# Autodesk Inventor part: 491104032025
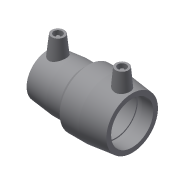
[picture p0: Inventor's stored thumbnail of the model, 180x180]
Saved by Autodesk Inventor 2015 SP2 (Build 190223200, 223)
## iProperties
Created: 2017-06
Part Number: 491104032025
Material: Generic
Description: PLASSON REDUCING COUPLER 32-25
Document SubType Name: Modeling
Designer: KIM
Mass: 54.8237 g
Surface Area: 155.252 cm^2
Volume: 54.8237 cm^3
Density: 1 g/cm^3
Appearance: Default
Author: KIM
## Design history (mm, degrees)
derived "491104.ipt"
feature "Solid1::491104.ipt"
tag "TaggingFeature1"
body "Solid1"
other parameters: "d0" = 81, "d2" = 36, "d3" = 35, "d4" = 21, "d5" = 32.4, "d7" = 25, "d8" = 168 deg, "d10" = 14, "d11" = 4.66667, "d13" = 81, "d14" = 17.6296, "d15" = 35, "d18" = 25, "d19" = 1.75, "d20" = 168 deg, "d22" = 108.92847, "d25" = 135 deg, "d29" = 39, "d30" = 15, "d31" = 28.35, "d34" = 6 deg, "d35" = 15, "d38" = 25.25, "d39" = 5 deg, "d41" = 4, "d42" = 14, "d43" = 0, "d45" = 4, "d46" = 14, "d47" = 0, "d48" = 36, "d49" = 32, "d50" = 45, "d52" = 22.5, "d53" = 16, "d54" = 5.33333, "d55" = 168 deg, "d56" = 24, "d58" = 40.5, "d59" = 1.75, "d60" = 135 deg, "d61" = 43, "d62" = 15, "d64" = 4, "d66" = 5 deg, "d67" = 14, "d68" = 0, "d69" = 28.35, "d70" = 36, "d71" = 45, "d73" = 42.3, "d76" = 1.75, "d77" = 168 deg, "d78" = 32, "d79" = 1.75, "d81" = 22.5, "d82" = 33.84, "d83" = 120 deg, "d88" = 15, "d89" = 25.4, "d90" = 5 deg, "d92" = 4, "d93" = 14, "d94" = 0, "d95" = 3, "d96" = 0, "d97" = 3, "d98" = 0, "d99" = 10.15, "d100" = 2.5375, "d101" = 32.8248, "d102" = 20 deg, "d103" = 11.6, "d104" = 2.9, "d105" = 41.031, "d106" = 3.60705, "d107" = 3, "d108" = 0, "d109" = 3, "d110" = 0, "d_1" = 25, "L_" = 81, "L_2" = 35, "D_1" = 36, "A_1" = 39, "d_2" = 12, "d_" = 32, "A_" = 43, "D_" = 45
